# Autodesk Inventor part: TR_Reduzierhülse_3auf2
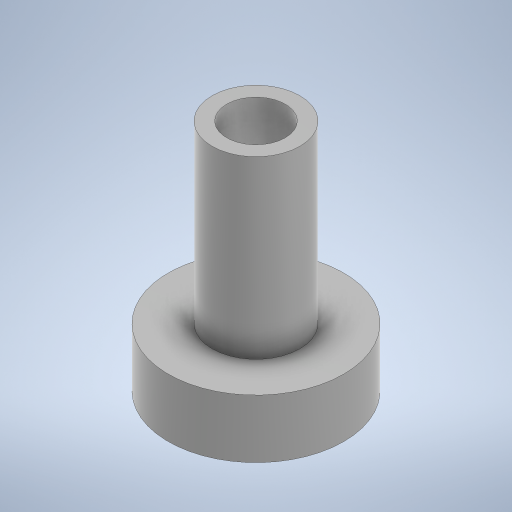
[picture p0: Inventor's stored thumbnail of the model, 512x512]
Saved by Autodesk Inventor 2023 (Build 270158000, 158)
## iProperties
Created: 2023-11
Part Number: TR_Reduzierhülse_3auf2
Material: PC/ABS-Kunststoff
Document SubType Name: Modeling
Designer: Administrator
Density: 0.357273 g/cm^3
Appearance: Glatt - Mittelgrau
Author: Administrator
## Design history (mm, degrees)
sketch "Skizze1"
  geometry: C1 r 1.5 at (0, 0); 1 further point
  constraints: 1 centre point, 1 coincident
  dimensions: "d0" = 3 diameter of C1
extrude "Extrusion1" new body sketch "Skizze1" distance "d1" = 6; taper "d2" = 0 deg
sketch "Skizze2"
  geometry: C1 r 3 at (0, 0); 1 further point
  constraints: 1 centre point, 1 coincident
  dimensions: "d3" = 6 diameter of C1
extrude "Extrusion2" join sketch "Skizze2" distance "d4" = 2; taper "d5" = 0 deg
sketch "Skizze3"
  geometry: C1 r 1 at (0, 0); 1 further point
  constraints: 1 centre point, 1 coincident
  dimensions: "d6" = 2 diameter of C1
extrude "Extrusion3" cut sketch "Skizze3" extent not by distance; stored distance "d7" = 0; taper "d8" = 0 deg
node "Volumenkörper1"
